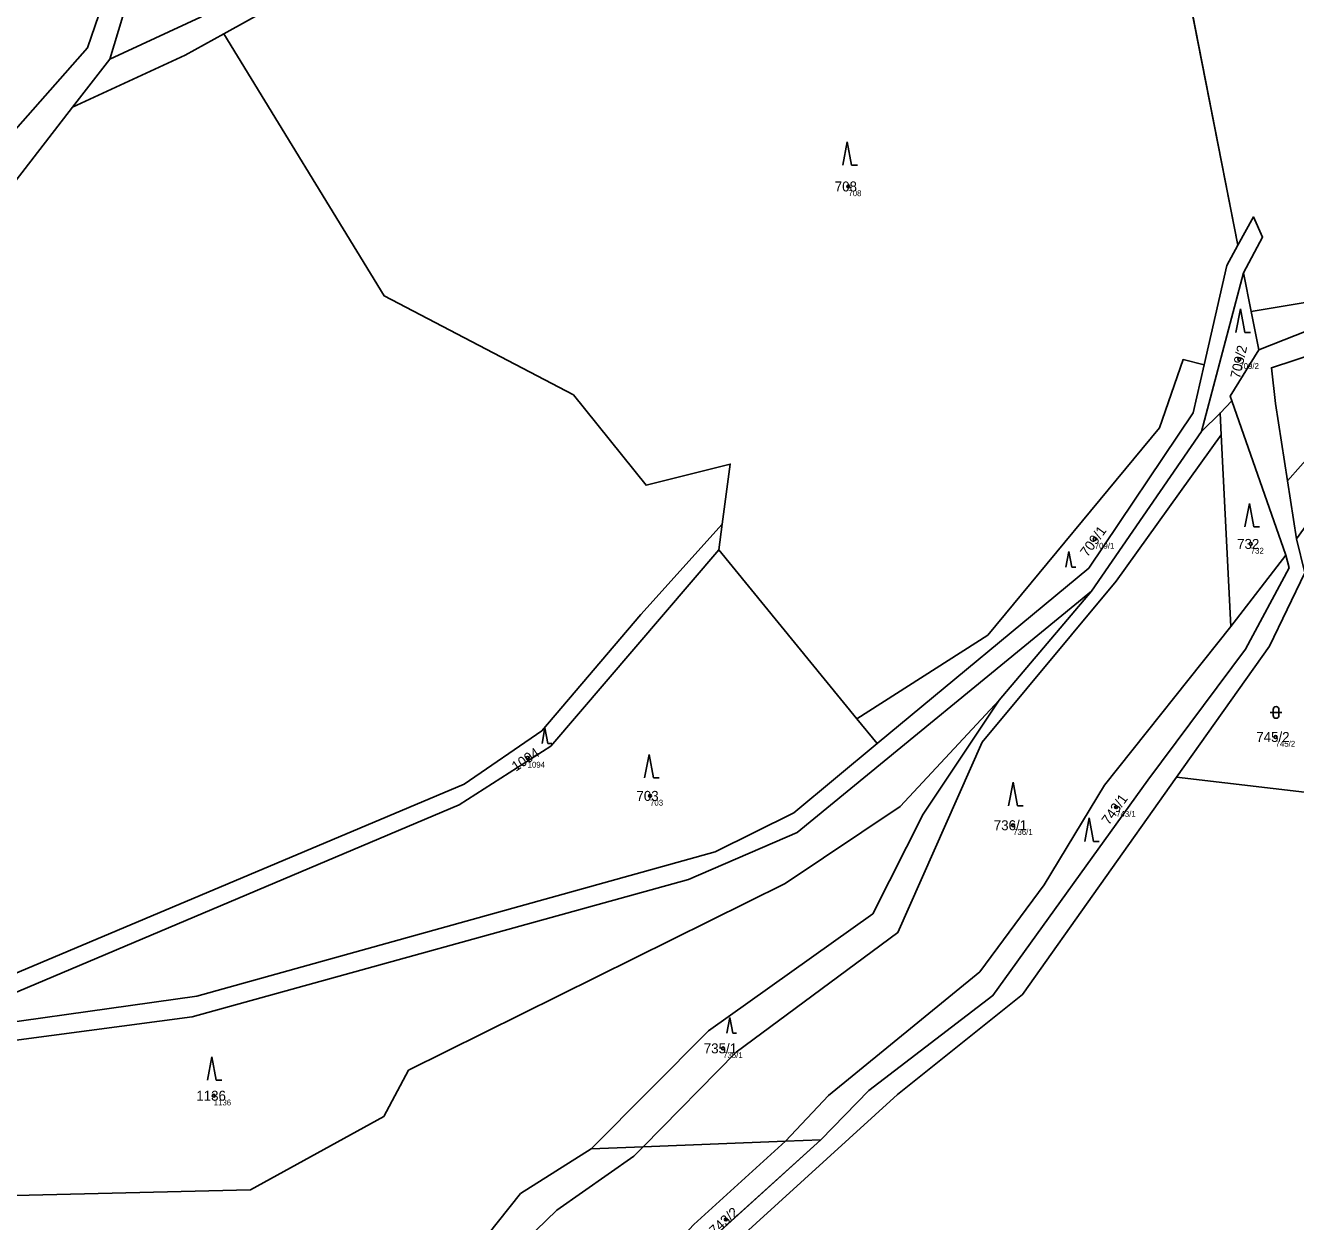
# Model space of a CAD drawing. Extents: x -554500 to -548272, y -1079733 to -1073730.
# Drawn here: x -552891.1 to -552674.2, y -1076720.4 to -1076516.2 of the extents above; entities that cross this region are included whole.
import ezdxf

# ---------------------------------------------------------------- set-up
doc = ezdxf.new("R2010")
doc.units = 0
for name, color, linetype in [('Definiční body', 7, 'Continuous'), ('Hranice parcel', 7, 'Continuous'), ('Parcelní čísla', 7, 'Continuous'), ('Polygon parcely', 7, 'Continuous'), ('Značky kultur', 7, 'Continuous')]:
    doc.layers.add(name, color=color, linetype=linetype)

msp = doc.modelspace()

# ---------------------------------------------------------------- linework, layer by layer
at = {"layer": 'Definiční body'}
for centre in [(-552750.59, -1076543.68994), (-552683.85, -1076573.17994), (-552708.53, -1076603.85994), (-552681.9, -1076604.69994), (-552677.66, -1076637.64994), (-552805.36, -1076641.22994), (-552784.45, -1076647.69994), (-552704.88, -1076649.60994), (-552722.47, -1076652.70994), (-552771.98, -1076690.78994), (-552858.94, -1076698.86994), (-552771.51, -1076719.98994)]:
    msp.add_circle(centre, 0.25, dxfattribs=at)
at = {"layer": 'Hranice parcel'}
for p, q in [((-552684.08, -1076553.72), (-552698.36, -1076481.06)), ((-552876.68, -1076521.95), (-552861.19, -1076514.79)), ((-552883.03, -1076530.17), (-552876.68, -1076521.95)), ((-552883.03, -1076530.17), (-552893.61, -1076543.86)), ((-552683.15, -1076558.42), (-552690.32, -1076585.5)), ((-552683.15, -1076558.42), (-552681.83, -1076565.04)), ((-552681.83, -1076565.04), (-552680.53, -1076571.59)), ((-552685.11, -1076580.27), (-552687.13, -1076582.36)), ((-552675.9, -1076606.59), (-552685.11, -1076580.27)), ((-552687.13, -1076582.36), (-552690.32, -1076585.5)), ((-552687.13, -1076582.36), (-552686.95, -1076586.08)), ((-552690.32, -1076585.5), (-552709.11, -1076612.75)), ((-552686.95, -1076586.08), (-552685.32, -1076618.8)), ((-552675.63, -1076593.95), (-552674.1, -1076603.82)), ((-552772.11, -1076601.33), (-552772.69, -1076605.72)), ((-552749.14, -1076634.54), (-552772.69, -1076605.72)), ((-552685.32, -1076618.8), (-552675.9, -1076606.59)), ((-552709.11, -1076612.75), (-552724.82, -1076631.37)), ((-552745.68, -1076638.77), (-552749.14, -1076634.54)), ((-552669.8, -1076647.4), (-552694.57, -1076644.52)), ((-552807.25, -1076753.41), (-552755.28, -1076706.38)), ((-552794.51, -1076707.91), (-552785.65, -1076707.57)), ((-552785.65, -1076707.57), (-552761.3, -1076706.62)), ((-552761.3, -1076706.62), (-552755.28, -1076706.38))]:
    msp.add_line(p, q, dxfattribs=at)
for points in [[(-553151.27, -1076562.64), (-553120.83, -1076572.45), (-553090.77, -1076572.01), (-553006.14, -1076561.87), (-552917.96, -1076546.36), (-552897.94, -1076539.79), (-552880.48, -1076520.05), (-552872.84, -1076497.78), (-552870.27, -1076476.37), (-552866.46, -1076461.58), (-552838.97, -1076422.91), (-552748.83, -1076317.24)], [(-552698.36, -1076481.06), (-552706.9, -1076472.48), (-552718.99, -1076468.64), (-552804.65, -1076500.24), (-552818.8, -1076503.85), (-552825.19, -1076499.86), (-552857.21, -1076517.62)], [(-552866.67, -1076474.4), (-552869.27, -1076497.44), (-552876.68, -1076521.95)], [(-552857.21, -1076517.62), (-552863.83, -1076521.29), (-552883.03, -1076530.17)], [(-552772.11, -1076601.33), (-552770.75, -1076591.06), (-552785.14, -1076594.68), (-552797.53, -1076579.28), (-552829.83, -1076562.38), (-552857.21, -1076517.62)], [(-552680.53, -1076571.59), (-552670.01, -1076567.43), (-552640.86, -1076547.83), (-552614.73, -1076534.83), (-552592.41, -1076528.61)], [(-552570.04, -1076534.1), (-552592.41, -1076531.92), (-552613.77, -1076538.47), (-552639.17, -1076551.08), (-552666.75, -1076570.81), (-552678.36, -1076574.64), (-552677.68, -1076580.73), (-552675.63, -1076593.95)], [(-552681.83, -1076565.04), (-552671.92, -1076563.36), (-552644.44, -1076545.91), (-552616.83, -1076533.42)], [(-552675.63, -1076593.95), (-552671.17, -1076588.94), (-552612.98, -1076556.28), (-552570.04, -1076534.1)], [(-552684.08, -1076553.72), (-552681.41, -1076548.9), (-552679.88, -1076552.32), (-552683.15, -1076558.42)], [(-552689.84, -1076574.14), (-552686, -1076557.19), (-552684.08, -1076553.72)], [(-552749.14, -1076634.54), (-552726.8, -1076620.27), (-552697.45, -1076584.86), (-552693.44, -1076573.25), (-552689.84, -1076574.14)], [(-552685.11, -1076580.27), (-552685.39, -1076579.48), (-552680.53, -1076571.59)], [(-552745.68, -1076638.77), (-552709.56, -1076608.86), (-552691.7, -1076582.35), (-552689.84, -1076574.14)], [(-552785.65, -1076707.57), (-552769.75, -1076691.41), (-552742.14, -1076671.04), (-552727.74, -1076638.55), (-552704.9, -1076611.06), (-552686.95, -1076586.08)], [(-552920.53, -1076689.68), (-552816.19, -1076645.7), (-552802.95, -1076636.62), (-552786, -1076616.73), (-552772.11, -1076601.33)], [(-552772.69, -1076605.72), (-552801.4, -1076639.22), (-552817.04, -1076649.22), (-552910.45, -1076688.73)], [(-552755.28, -1076706.38), (-552747.09, -1076697.96), (-552725.91, -1076681.77), (-552699.48, -1076645.02), (-552682.82, -1076622.66), (-552675.36, -1076608.79), (-552675.9, -1076606.59)], [(-552672.69, -1076609.64), (-552678.7, -1076622.12), (-552694.57, -1076644.52)], [(-553098.85, -1076711.9), (-552980.39, -1076705.28), (-552939.43, -1076698.63), (-552921.85, -1076693.28), (-552862.63, -1076685.38), (-552777.87, -1076661.95), (-552759.32, -1076653.97), (-552709.11, -1076612.75)], [(-552761.3, -1076706.62), (-552753.97, -1076698.85), (-552728.17, -1076677.71), (-552717.19, -1076662.89), (-552706.87, -1076645.88), (-552685.32, -1076618.8)], [(-552937.81, -1076716.99), (-552852.69, -1076714.91), (-552829.92, -1076702.39), (-552825.68, -1076694.53), (-552761.39, -1076662.66), (-552741.74, -1076649.53), (-552724.82, -1076631.37)], [(-552724.82, -1076631.37), (-552737.8, -1076650.84), (-552746.41, -1076667.81), (-552774.47, -1076687.77), (-552794.51, -1076707.91)], [(-552910.45, -1076688.73), (-552861.83, -1076681.9), (-552773.31, -1076657.24), (-552759.93, -1076650.57), (-552745.68, -1076638.77)], [(-552694.57, -1076644.52), (-552720.84, -1076681.61), (-552742.22, -1076698.68), (-552802.53, -1076753.57)], [(-552839.59, -1076742.27), (-552811.06, -1076728.76), (-552800.36, -1076718.42), (-552787.22, -1076709.16), (-552785.65, -1076707.57)], [(-552794.51, -1076707.91), (-552806.55, -1076715.56), (-552814.09, -1076724.99), (-552828.07, -1076731.05), (-552839.59, -1076742.27)], [(-552807.25, -1076753.41), (-552776.98, -1076720.85), (-552761.3, -1076706.62)]]:
    msp.add_lwpolyline(points, dxfattribs=at)
at = {"layer": 'Polygon parcely'}
for points in [[(-552521.66, -1076364.88), (-552602.38, -1076421.42), (-552661.47, -1076438.8), (-552706.74, -1076447.12), (-552805.86, -1076483.29), (-552823.87, -1076492.01), (-552861.19, -1076514.79), (-552876.68, -1076521.95), (-552883.03, -1076530.17), (-552863.83, -1076521.29), (-552857.21, -1076517.62), (-552825.19, -1076499.86), (-552818.8, -1076503.85), (-552804.65, -1076500.24), (-552718.99, -1076468.64), (-552706.9, -1076472.48), (-552698.36, -1076481.06), (-552701.24, -1076466.42), (-552713.29, -1076462.89), (-552618.03, -1076437.64), (-552610.94, -1076435.25), (-552601.23, -1076431.08), (-552593.59, -1076427.89), (-552525.71, -1076388.4)], [(-553293.76, -1076560.13), (-553237.18, -1076545.81), (-553224.08, -1076542.05), (-553198.04, -1076540.33), (-553173.25, -1076558.82), (-553157.04, -1076567.06), (-553129.44, -1076577.39), (-553117.15, -1076579.15), (-553110.55, -1076580.09), (-553030.13, -1076571.68), (-552922.19, -1076551.33), (-552893.61, -1076543.86), (-552883.03, -1076530.17), (-552876.68, -1076521.95), (-552869.27, -1076497.44)], [(-552872.84, -1076497.78), (-552880.48, -1076520.05), (-552897.94, -1076539.79), (-552917.96, -1076546.36), (-553006.14, -1076561.87), (-553090.77, -1076572.01), (-553120.83, -1076572.45), (-553151.27, -1076562.64), (-553174.94, -1076552.5), (-553195.69, -1076533.46), (-553223.72, -1076537.63), (-553294.23, -1076556.34)], [(-553119.01, -1076511.92), (-553151.93, -1076519.94), (-553177.03, -1076528.61), (-553180.2, -1076536.13), (-553174.97, -1076546.01), (-553151.27, -1076562.64), (-553120.83, -1076572.45), (-553090.77, -1076572.01), (-553006.14, -1076561.87), (-552917.96, -1076546.36), (-552897.94, -1076539.79), (-552880.48, -1076520.05), (-552872.84, -1076497.78)], [(-552920.53, -1076689.68), (-552816.19, -1076645.7), (-552802.95, -1076636.62), (-552786, -1076616.73), (-552772.11, -1076601.33), (-552770.75, -1076591.06), (-552785.14, -1076594.68), (-552797.53, -1076579.28), (-552829.83, -1076562.38), (-552857.21, -1076517.62), (-552863.83, -1076521.29), (-552883.03, -1076530.17), (-552893.61, -1076543.86)], [(-552541.94, -1076528.83), (-552551.15, -1076533.06), (-552577.9, -1076529.28), (-552592.41, -1076528.61), (-552614.73, -1076534.83), (-552640.86, -1076547.83), (-552670.01, -1076567.43), (-552680.53, -1076571.59), (-552685.39, -1076579.48), (-552685.11, -1076580.27), (-552675.9, -1076606.59), (-552675.36, -1076608.79), (-552682.82, -1076622.66), (-552699.48, -1076645.02), (-552725.91, -1076681.77), (-552747.09, -1076697.96), (-552755.28, -1076706.38), (-552807.25, -1076753.41)], [(-552802.53, -1076753.57), (-552742.22, -1076698.68), (-552720.84, -1076681.61), (-552694.57, -1076644.52), (-552678.7, -1076622.12), (-552672.69, -1076609.64), (-552674.1, -1076603.82), (-552675.63, -1076593.95), (-552677.68, -1076580.73), (-552678.36, -1076574.64), (-552666.75, -1076570.81), (-552639.17, -1076551.08), (-552613.77, -1076538.47), (-552592.41, -1076531.92), (-552570.04, -1076534.1), (-552556.35, -1076535.43), (-552523.34, -1076533.93)], [(-552921.85, -1076693.28), (-552862.63, -1076685.38), (-552777.87, -1076661.95), (-552759.32, -1076653.97), (-552709.11, -1076612.75), (-552690.32, -1076585.5), (-552683.15, -1076558.42), (-552679.88, -1076552.32), (-552681.41, -1076548.9), (-552684.08, -1076553.72), (-552686, -1076557.19), (-552689.84, -1076574.14), (-552691.7, -1076582.35), (-552709.56, -1076608.86), (-552745.68, -1076638.77), (-552759.93, -1076650.57), (-552773.31, -1076657.24), (-552861.83, -1076681.9), (-552910.45, -1076688.73)]]:
    msp.add_lwpolyline(points, dxfattribs=at)
for points in [[(-552671.92, -1076563.36), (-552644.44, -1076545.91), (-552616.83, -1076533.42), (-552607.55, -1076526.7), (-552609.35, -1076524.22), (-552607.13, -1076493.71), (-552602.77, -1076462.46), (-552606.68, -1076454.87), (-552601.23, -1076431.08), (-552610.94, -1076435.25), (-552618.03, -1076437.64), (-552701.4, -1076465.61), (-552701.24, -1076466.42), (-552698.36, -1076481.06), (-552684.08, -1076553.72), (-552681.41, -1076548.9), (-552679.88, -1076552.32), (-552683.15, -1076558.42), (-552681.83, -1076565.04)], [(-552693.44, -1076573.25), (-552689.84, -1076574.14), (-552686, -1076557.19), (-552684.08, -1076553.72), (-552698.36, -1076481.06), (-552706.9, -1076472.48), (-552718.99, -1076468.64), (-552804.65, -1076500.24), (-552818.8, -1076503.85), (-552825.19, -1076499.86), (-552857.21, -1076517.62), (-552829.83, -1076562.38), (-552797.53, -1076579.28), (-552785.14, -1076594.68), (-552770.75, -1076591.06), (-552772.11, -1076601.33), (-552772.69, -1076605.72), (-552749.14, -1076634.54), (-552726.8, -1076620.27), (-552697.45, -1076584.86)], [(-552876.68, -1076521.95), (-552861.19, -1076514.79), (-552866.67, -1076474.4), (-552869.27, -1076497.44)], [(-552670.01, -1076567.43), (-552640.86, -1076547.83), (-552614.73, -1076534.83), (-552592.41, -1076528.61), (-552586.77, -1076526.37), (-552596.9, -1076524.56), (-552616.83, -1076533.42), (-552644.44, -1076545.91), (-552671.92, -1076563.36), (-552681.83, -1076565.04), (-552680.53, -1076571.59)], [(-552666.75, -1076570.81), (-552678.36, -1076574.64), (-552677.68, -1076580.73), (-552675.63, -1076593.95), (-552671.17, -1076588.94), (-552612.98, -1076556.28), (-552570.04, -1076534.1), (-552592.41, -1076531.92), (-552613.77, -1076538.47), (-552639.17, -1076551.08)], [(-552570.04, -1076534.1), (-552612.98, -1076556.28), (-552671.17, -1076588.94), (-552675.63, -1076593.95), (-552674.1, -1076603.82), (-552669.45, -1076597.48), (-552664.86, -1076591.22), (-552649.36, -1076581.64), (-552611.72, -1076561.31), (-552556.35, -1076535.43)], [(-552685.11, -1076580.27), (-552685.39, -1076579.48), (-552680.53, -1076571.59), (-552681.83, -1076565.04), (-552683.15, -1076558.42), (-552690.32, -1076585.5), (-552687.13, -1076582.36)], [(-552691.7, -1076582.35), (-552689.84, -1076574.14), (-552693.44, -1076573.25), (-552697.45, -1076584.86), (-552726.8, -1076620.27), (-552749.14, -1076634.54), (-552745.68, -1076638.77), (-552709.56, -1076608.86)], [(-552675.9, -1076606.59), (-552685.11, -1076580.27), (-552687.13, -1076582.36), (-552686.95, -1076586.08), (-552685.32, -1076618.8)], [(-552709.11, -1076612.75), (-552724.82, -1076631.37), (-552737.8, -1076650.84), (-552746.41, -1076667.81), (-552774.47, -1076687.77), (-552794.51, -1076707.91), (-552785.65, -1076707.57), (-552769.75, -1076691.41), (-552742.14, -1076671.04), (-552727.74, -1076638.55), (-552704.9, -1076611.06), (-552686.95, -1076586.08), (-552687.13, -1076582.36), (-552690.32, -1076585.5)], [(-552728.17, -1076677.71), (-552717.19, -1076662.89), (-552706.87, -1076645.88), (-552685.32, -1076618.8), (-552686.95, -1076586.08), (-552704.9, -1076611.06), (-552727.74, -1076638.55), (-552742.14, -1076671.04), (-552769.75, -1076691.41), (-552785.65, -1076707.57), (-552761.3, -1076706.62), (-552753.97, -1076698.85)], [(-552910.45, -1076688.73), (-552817.04, -1076649.22), (-552801.4, -1076639.22), (-552772.69, -1076605.72), (-552772.11, -1076601.33), (-552786, -1076616.73), (-552802.95, -1076636.62), (-552816.19, -1076645.7), (-552920.53, -1076689.68)], [(-552773.31, -1076657.24), (-552759.93, -1076650.57), (-552745.68, -1076638.77), (-552749.14, -1076634.54), (-552772.69, -1076605.72), (-552801.4, -1076639.22), (-552817.04, -1076649.22), (-552910.45, -1076688.73), (-552861.83, -1076681.9)], [(-552675.36, -1076608.79), (-552675.9, -1076606.59), (-552685.32, -1076618.8), (-552706.87, -1076645.88), (-552717.19, -1076662.89), (-552728.17, -1076677.71), (-552753.97, -1076698.85), (-552761.3, -1076706.62), (-552755.28, -1076706.38), (-552747.09, -1076697.96), (-552725.91, -1076681.77), (-552699.48, -1076645.02), (-552682.82, -1076622.66)], [(-552678.7, -1076622.12), (-552694.57, -1076644.52), (-552669.8, -1076647.4), (-552667.82, -1076629.78), (-552672.69, -1076609.64)], [(-552761.39, -1076662.66), (-552741.74, -1076649.53), (-552724.82, -1076631.37), (-552709.11, -1076612.75), (-552759.32, -1076653.97), (-552777.87, -1076661.95), (-552862.63, -1076685.38), (-552921.85, -1076693.28), (-552939.43, -1076698.63), (-552980.39, -1076705.28), (-553098.85, -1076711.9), (-553084.6, -1076715.45), (-552999.87, -1076711.28), (-552975.92, -1076713.65), (-552942.15, -1076708.95), (-552937.05, -1076708.24), (-552937.81, -1076716.99), (-552852.69, -1076714.91), (-552829.92, -1076702.39), (-552825.68, -1076694.53)], [(-552842.7, -1076753.67), (-552839.59, -1076742.27), (-552828.07, -1076731.05), (-552814.09, -1076724.99), (-552806.55, -1076715.56), (-552794.51, -1076707.91), (-552774.47, -1076687.77), (-552746.41, -1076667.81), (-552737.8, -1076650.84), (-552724.82, -1076631.37), (-552741.74, -1076649.53), (-552761.39, -1076662.66), (-552825.68, -1076694.53), (-552829.92, -1076702.39), (-552852.69, -1076714.91), (-552937.81, -1076716.99), (-552941, -1076753.93), (-552911.43, -1076753.82), (-552882.42, -1076753.7), (-552853.38, -1076753.74)], [(-552720.84, -1076681.61), (-552742.22, -1076698.68), (-552802.53, -1076753.57), (-552807.44, -1076758.04), (-552798.41, -1076769.47), (-552782.64, -1076768.18), (-552770.99, -1076773.38), (-552771.17, -1076793.34), (-552745.32, -1076799.56), (-552709.01, -1076798.45), (-552688.06, -1076798.63), (-552669.87, -1076796.53), (-552643.31, -1076782.96), (-552618.04, -1076776.84), (-552620.31, -1076767.74), (-552628.49, -1076753.02), (-552630.07, -1076741.43), (-552629.55, -1076729.8), (-552644.98, -1076713.39), (-552660.65, -1076680.06), (-552660.92, -1076659.58), (-552669.8, -1076647.4), (-552694.57, -1076644.52)], [(-552776.98, -1076720.85), (-552761.3, -1076706.62), (-552785.65, -1076707.57), (-552787.22, -1076709.16), (-552800.36, -1076718.42), (-552811.06, -1076728.76), (-552839.59, -1076742.27), (-552842.7, -1076753.67), (-552807.25, -1076753.41)], [(-552800.36, -1076718.42), (-552787.22, -1076709.16), (-552785.65, -1076707.57), (-552794.51, -1076707.91), (-552806.55, -1076715.56), (-552814.09, -1076724.99), (-552828.07, -1076731.05), (-552839.59, -1076742.27), (-552811.06, -1076728.76)], [(-552807.25, -1076753.41), (-552755.28, -1076706.38), (-552761.3, -1076706.62), (-552776.98, -1076720.85)]]:
    msp.add_lwpolyline(points, close=True, dxfattribs=at)
at = {"layer": 'Značky kultur'}
for p, q in [((-552750.78, -1076536.06), (-552751.53, -1076540.06)), ((-552750.03, -1076540.06), (-552750.78, -1076536.06)), ((-552750.03, -1076540.06), (-552749.034, -1076540.06)), ((-552683.67, -1076564.6), (-552684.42, -1076568.6)), ((-552682.92, -1076568.6), (-552683.67, -1076564.6)), ((-552682.92, -1076568.6), (-552681.924, -1076568.6)), ((-552682.13, -1076597.78), (-552682.88, -1076601.78)), ((-552681.38, -1076601.78), (-552682.13, -1076597.78)), ((-552681.38, -1076601.78), (-552680.384, -1076601.78)), ((-552712.94, -1076605.98), (-552713.442, -1076608.66)), ((-552712.438, -1076608.66), (-552712.94, -1076605.98)), ((-552712.438, -1076608.66), (-552711.77, -1076608.66)), ((-552678.581, -1076633.451), (-552676.579, -1076633.451)), ((-552678.081, -1076632.951), (-552678.081, -1076633.952)), ((-552677.079, -1076633.952), (-552677.079, -1076632.951)), ((-552802.39, -1076636.1), (-552802.892, -1076638.78)), ((-552801.888, -1076638.78), (-552802.39, -1076636.1)), ((-552801.888, -1076638.78), (-552801.22, -1076638.78)), ((-552784.62, -1076640.63), (-552785.37, -1076644.63)), ((-552783.87, -1076644.63), (-552784.62, -1076640.63)), ((-552783.87, -1076644.63), (-552782.874, -1076644.63)), ((-552722.48, -1076645.37), (-552723.23, -1076649.37)), ((-552721.73, -1076649.37), (-552722.48, -1076645.37)), ((-552721.73, -1076649.37), (-552720.734, -1076649.37)), ((-552709.5, -1076651.47), (-552710.25, -1076655.47)), ((-552708.75, -1076655.47), (-552709.5, -1076651.47)), ((-552708.75, -1076655.47), (-552707.754, -1076655.47)), ((-552770.84, -1076685.53), (-552771.342, -1076688.21)), ((-552770.338, -1076688.21), (-552770.84, -1076685.53)), ((-552770.338, -1076688.21), (-552769.67, -1076688.21)), ((-552859.28, -1076692.23), (-552860.03, -1076696.23)), ((-552858.53, -1076696.23), (-552859.28, -1076692.23)), ((-552858.53, -1076696.23), (-552857.534, -1076696.23))]:
    msp.add_line(p, q, dxfattribs=at)
for centre, start, end in [((-552677.58, -1076632.9509), 0, 180), ((-552677.58, -1076633.9509), 180, 359.9878861)]:
    msp.add_arc(centre, 0.5, start, end, dxfattribs=at)

# ---------------------------------------------------------------- texts
at = {"layer": 'Definiční body'}
for s, p in [('708', (-552750.59, -1076545.346)), ('709/2', (-552683.85, -1076574.836)), ('709/1', (-552708.53, -1076605.516)), ('732', (-552681.9, -1076606.356)), ('745/2', (-552677.66, -1076639.306)), ('1094', (-552805.36, -1076642.886)), ('703', (-552784.45, -1076649.356)), ('743/1', (-552704.88, -1076651.266)), ('736/1', (-552722.47, -1076654.366)), ('735/1', (-552771.98, -1076692.446)), ('1136', (-552858.94, -1076700.526))]:
    msp.add_text(s, height=0.999996, dxfattribs=at).set_placement(p)
at = {"layer": 'Parcelní čísla'}
for s, p in [('708', (-552752.915, -1076544.54)), ('732', (-552684.225, -1076605.55)), ('745/2', (-552680.958, -1076638.5)), ('703', (-552786.775, -1076648.55)), ('736/1', (-552725.768, -1076653.56)), ('735/1', (-552775.278, -1076691.64)), ('1136', (-552861.914, -1076699.72))]:
    msp.add_text(s, height=1.699998, dxfattribs=at).set_placement(p)
for s, rotation, p in [('709/2', 77, (-552683.763, -1076576.585)), ('709/1', 54, (-552709.781, -1076607.028)), ('1094', 34, (-552807.35, -1076643.597)), ('743/1', 54, (-552706.131, -1076652.778)), ('743/2', 42, (-552773.392, -1076722.828))]:
    msp.add_text(s, height=1.699998, rotation=rotation, dxfattribs=at).set_placement(p)

doc.saveas('drawing.dxf')
